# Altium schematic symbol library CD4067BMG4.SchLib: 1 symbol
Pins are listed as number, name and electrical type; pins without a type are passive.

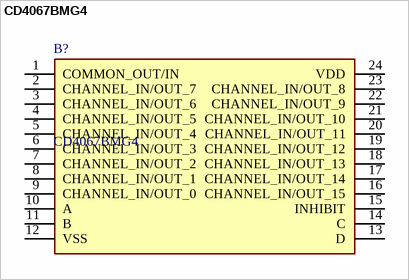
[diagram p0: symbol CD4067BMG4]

## CD4067BMG4
designator B?
IC MUX/DEMUX 1X16 24SOIC; Manufacturer_Name: Texas Instruments; Geometry.Height: 2.65mm
footprint SOIC127P1030X265-24N
pins: 1 COMMON_OUT/IN, 2 CHANNEL_IN/OUT_7, 3 CHANNEL_IN/OUT_6, 4 CHANNEL_IN/OUT_5, 5 CHANNEL_IN/OUT_4, 6 CHANNEL_IN/OUT_3, 7 CHANNEL_IN/OUT_2, 8 CHANNEL_IN/OUT_1, 9 CHANNEL_IN/OUT_0, 10 A, 11 B, 12 VSS, 13 D, 14 C, 15 INHIBIT, 16 CHANNEL_IN/OUT_15, 17 CHANNEL_IN/OUT_14, 18 CHANNEL_IN/OUT_13, 19 CHANNEL_IN/OUT_12, 20 CHANNEL_IN/OUT_11, 21 CHANNEL_IN/OUT_10, 22 CHANNEL_IN/OUT_9, 23 CHANNEL_IN/OUT_8, 24 VDD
